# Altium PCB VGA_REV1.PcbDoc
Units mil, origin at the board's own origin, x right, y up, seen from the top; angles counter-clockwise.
Board outline 4435 x 3240 mil, 4 copper layers (Top Layer, MidLayer1, InternalPlane1, Bottom Layer); 47 components, 28 nets, 151 pads, 48 vias.
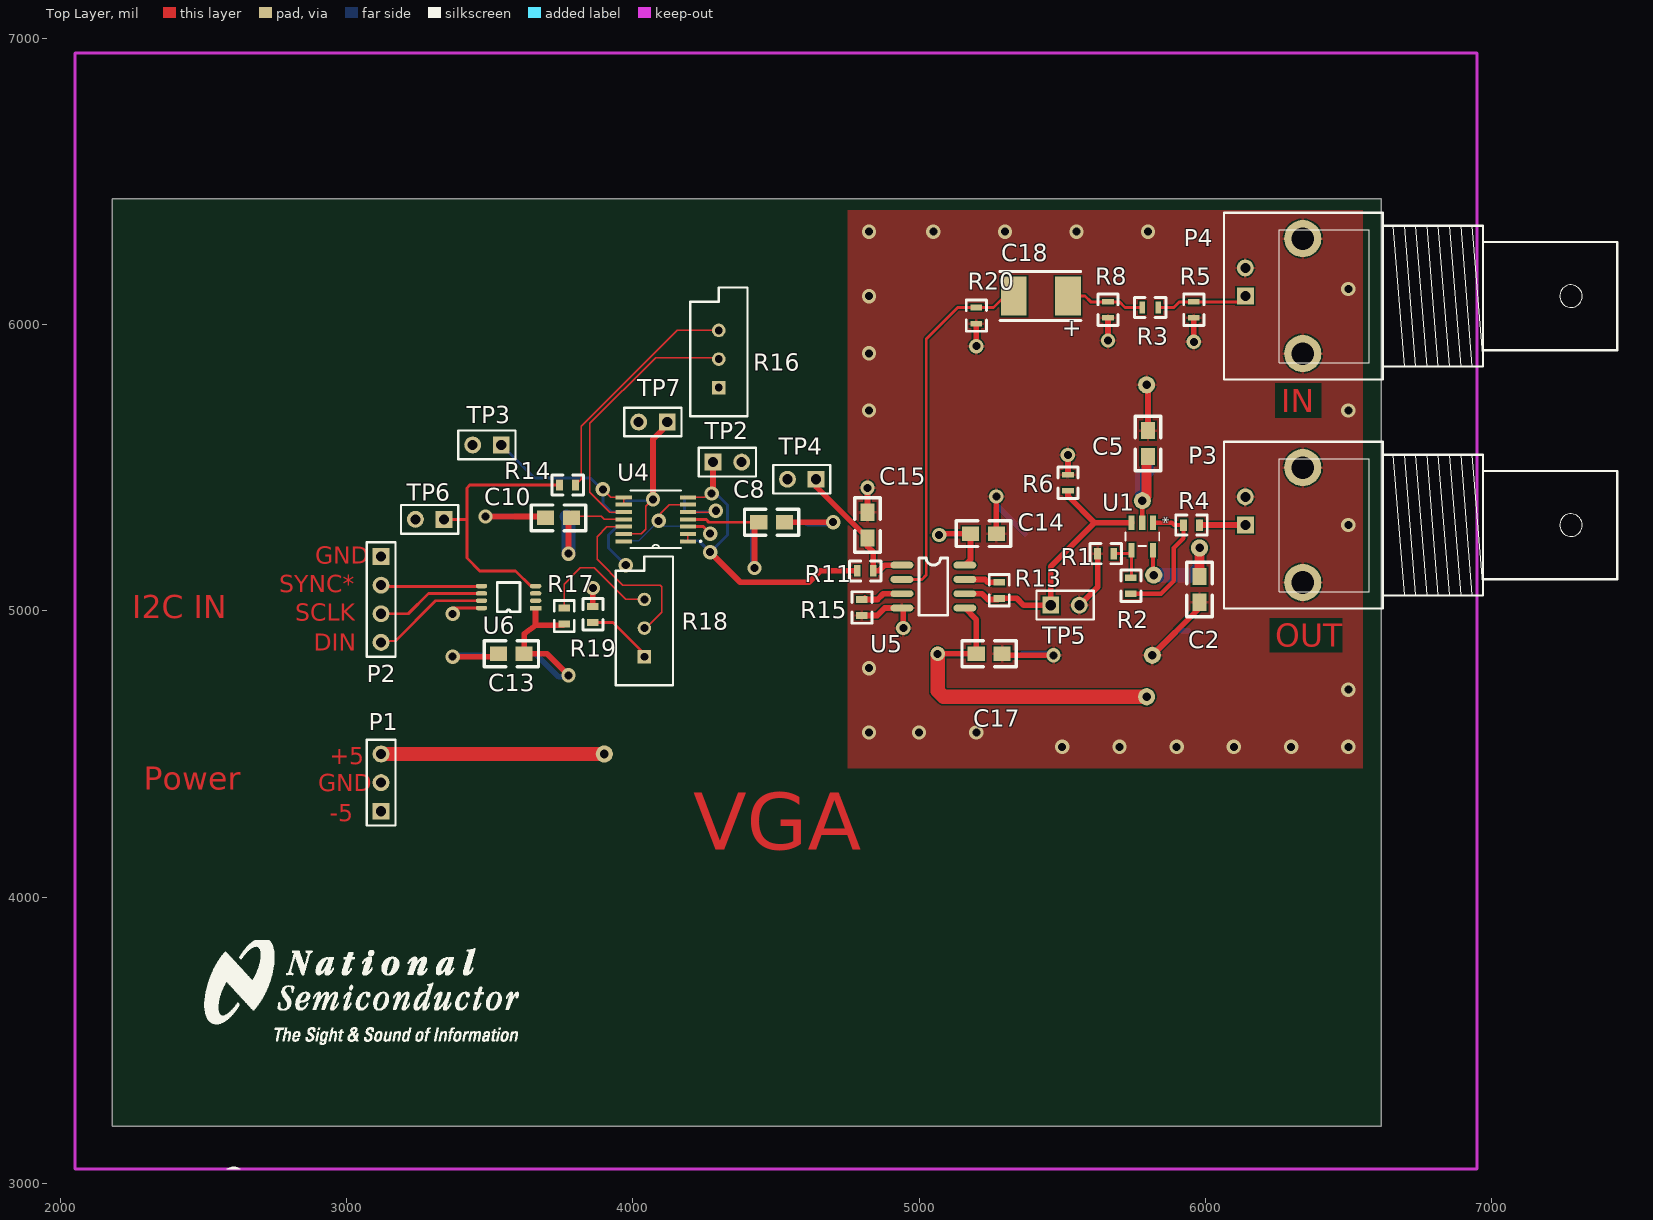
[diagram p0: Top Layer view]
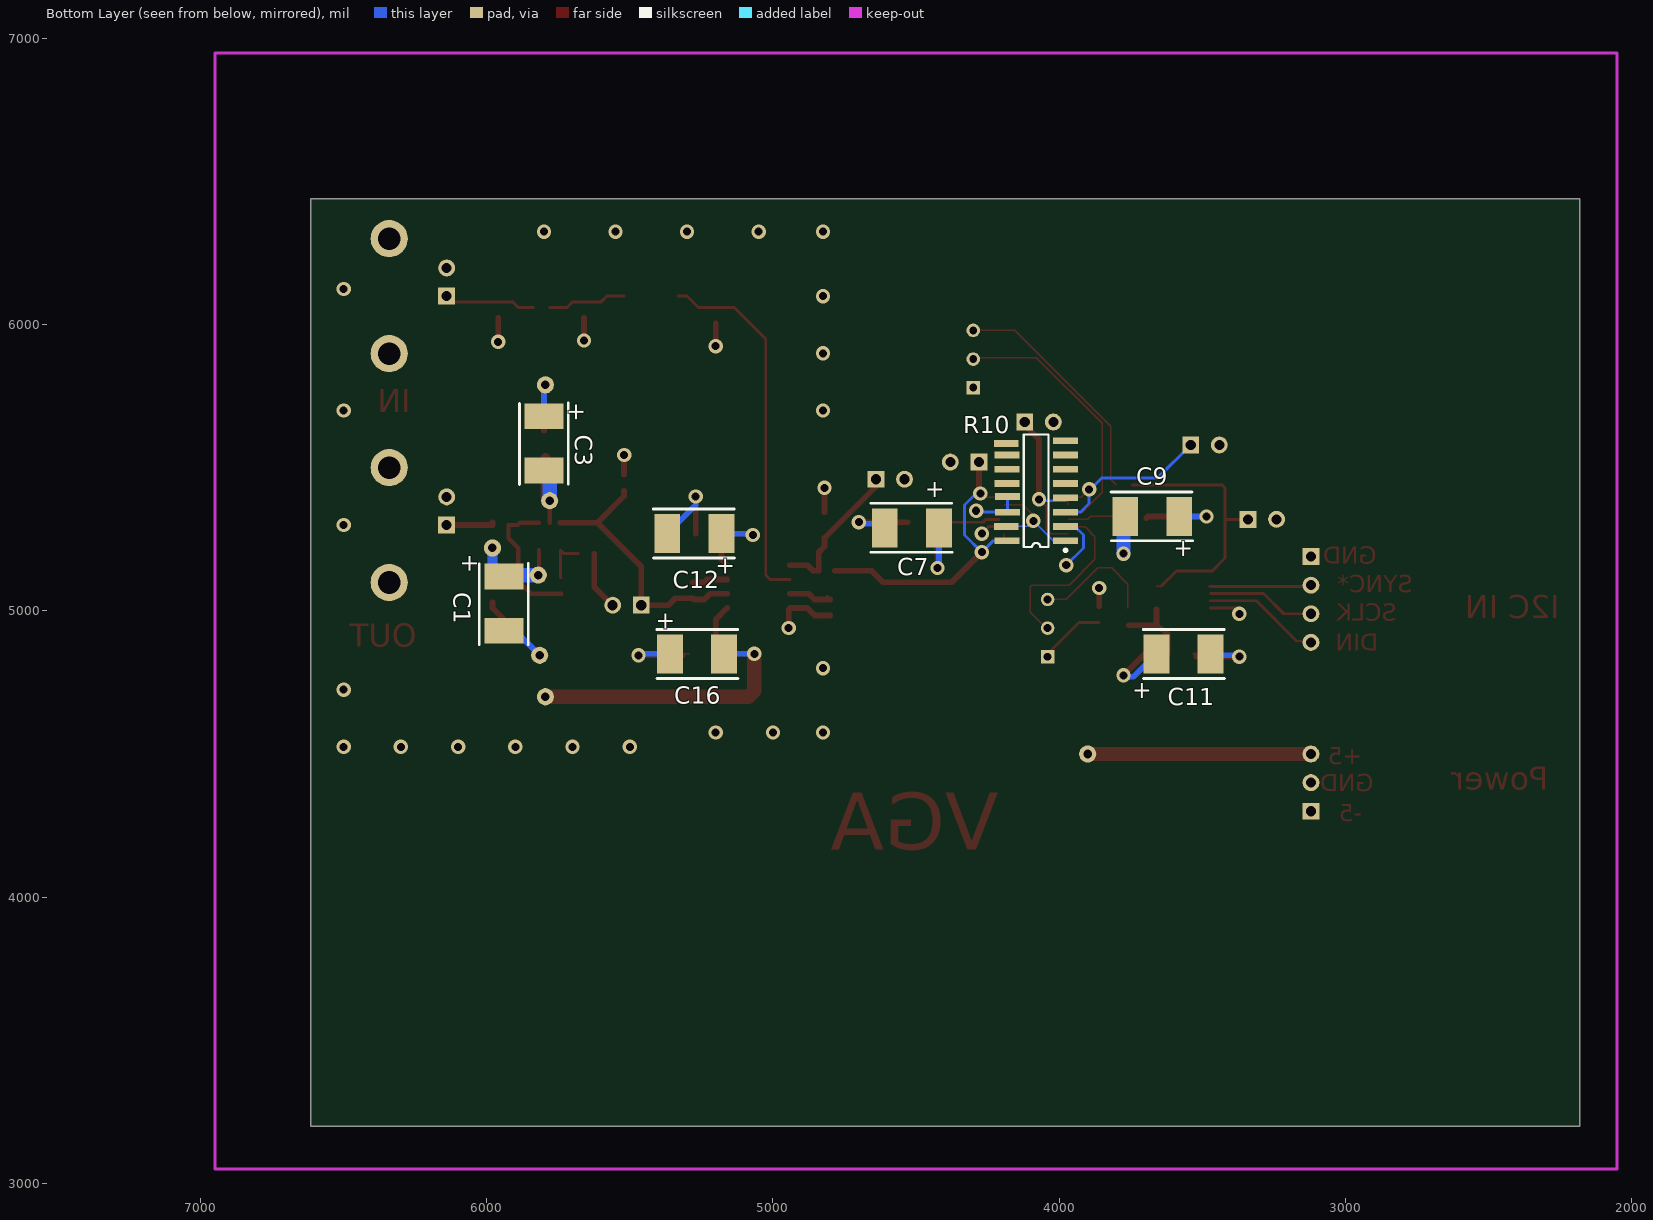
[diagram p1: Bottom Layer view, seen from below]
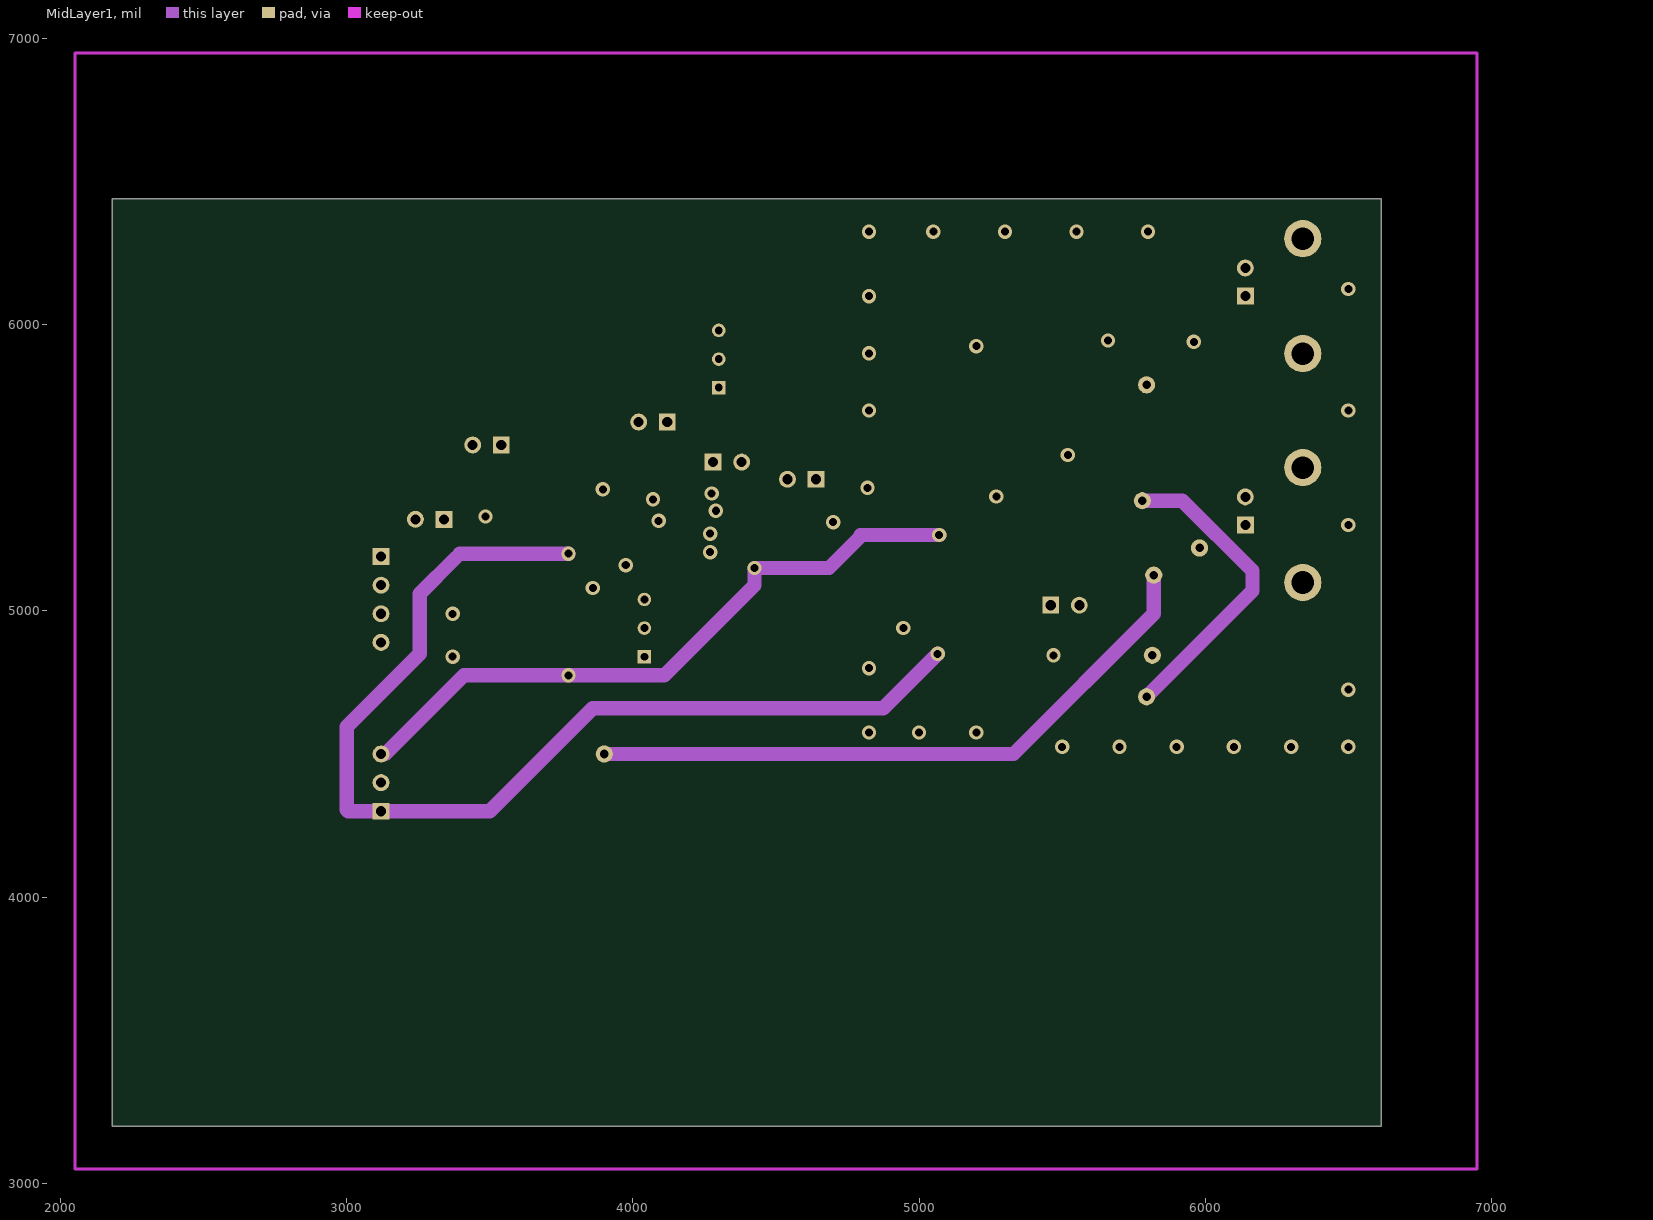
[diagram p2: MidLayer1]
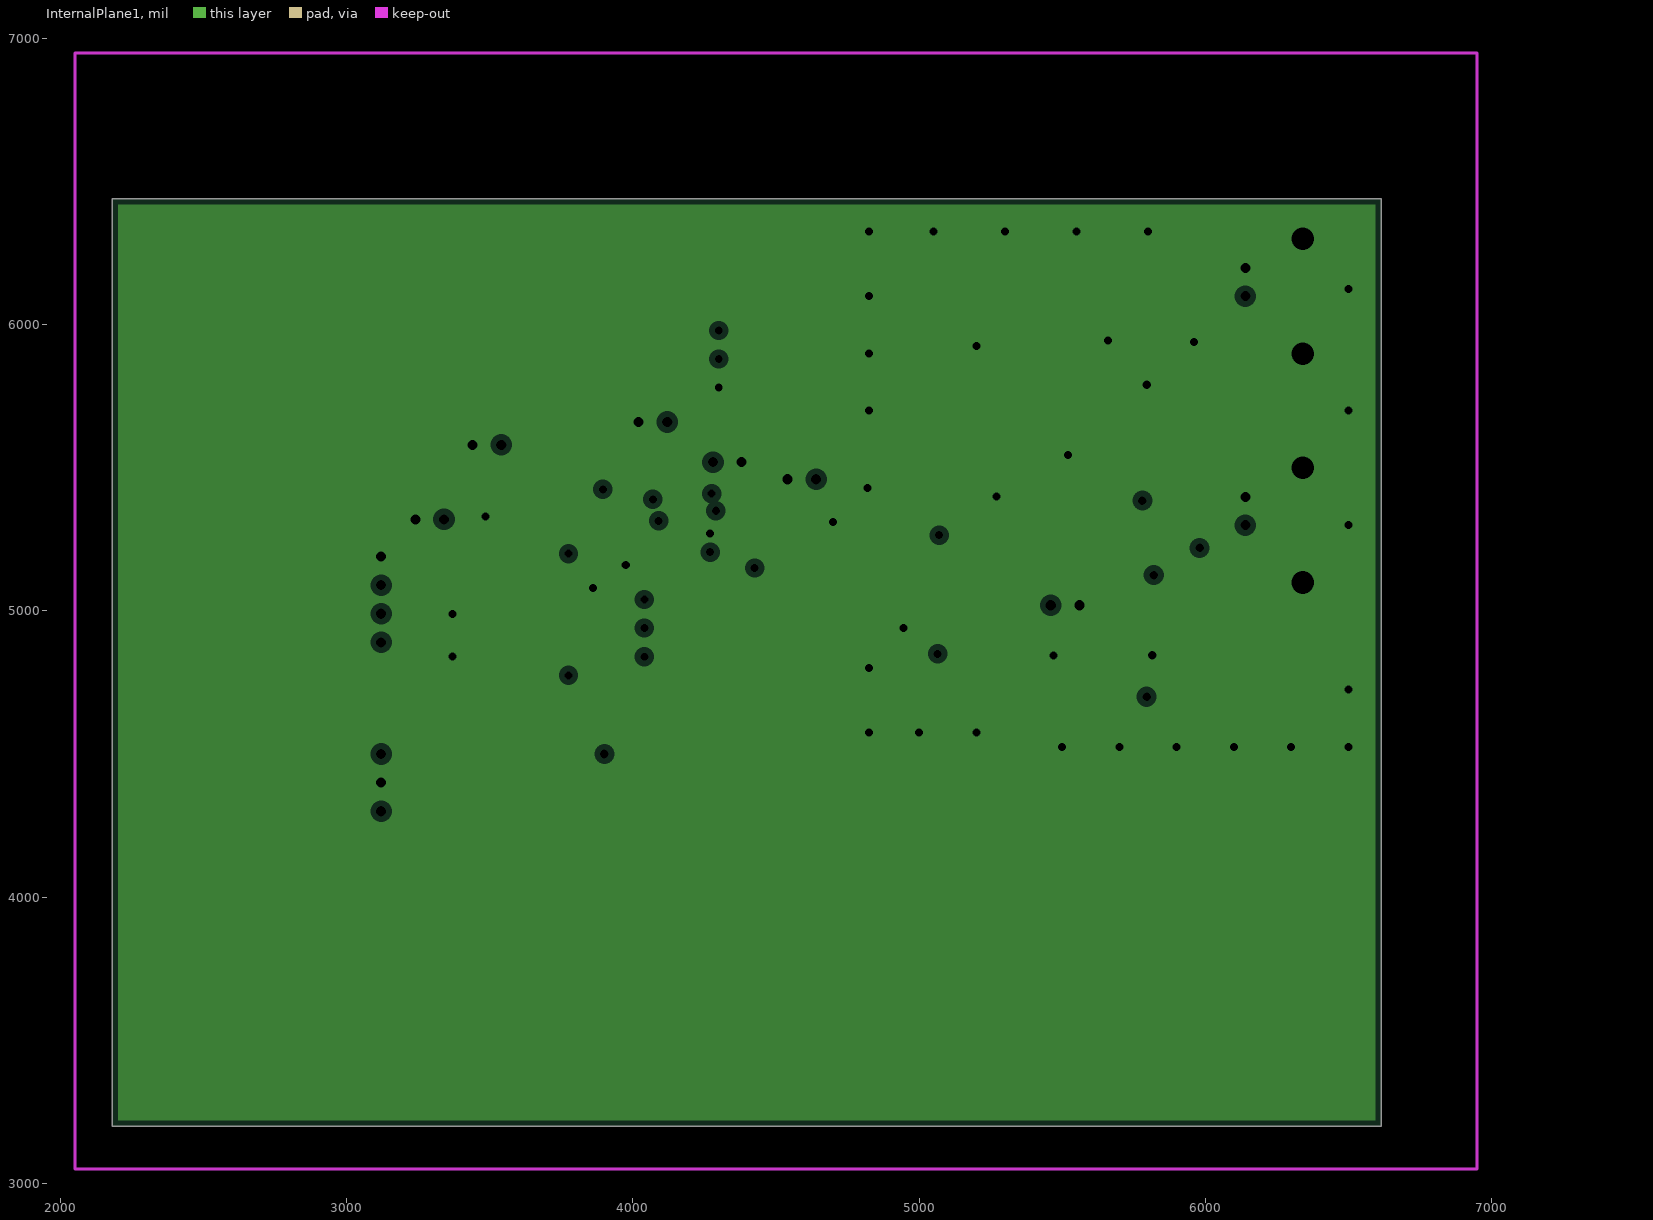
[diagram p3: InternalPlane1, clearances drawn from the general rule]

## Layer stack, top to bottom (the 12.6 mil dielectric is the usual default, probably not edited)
Top Layer: signal copper 1.4
Dielectric: core 12.6, FR-4, Dk 4.8
MidLayer1: signal copper 1.4
Dielectric: prepreg 12.6, FR-4, Dk 4.8
InternalPlane1: plane copper 1.4, net GND
Dielectric: core 12.6, FR-4, Dk 4.8
Bottom Layer: signal copper 1.4

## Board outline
6615,3200 6615,6440 2180,6440 2180,3200

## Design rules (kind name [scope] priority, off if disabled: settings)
Clearance [All] p1: gap=5
ComponentClearance [All] p1: gap=5 collisioncheckmode=3 verticalgap=5
PlaneClearance [All] p1: clearance=20
PlaneConnect [All] p1: planeconnectstyle=Relief reliefexpansion=20 reliefentries=4 reliefconductorwidth=10 reliefairgap=10
PolygonConnect [All] p1: connectstyle=Relief reliefconductorwidth=10 reliefentries=4 polygonreliefangle="90 Angle"
RoutingVias [All] p1: holewidth=25 width=40 viastyle="Through Hole" minholewidth=28 minwidth=50 maxholewidth=28 maxwidth=50
SolderMaskExpansion [All] p1: expansion=4
TestPointUsage [All] p1: valid=0 allowmultiple=FALSE
Testpoint [All] p1: side=15 testpointundercomponent=TRUE minsize=40 maxsize=100 preferedsize=60 minholesize=0 maxholesize=40 preferedholesize=32 testpointgrid=1 style=1023 order=0123456789
Width "Width for V+" [(InNet('V+'))] p1: maxlimit=50 minlimit=10 preferedwidth=10 midlayer1_prefwidth=50 minimp=50.000000 maximp=50.000000 favimp=50.000000
Width [All] p2: maxlimit=50 minlimit=5 preferedwidth=5 minimp=50.000000 maximp=50.000000 favimp=50.000000
16 further rules are at their usual default settings.

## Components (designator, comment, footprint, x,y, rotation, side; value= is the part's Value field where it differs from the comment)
C1 "Cap Pol1" TANT-C 5940,5120 r270 bottom
C2 "Cap" 0805 5980,5120 r270 top
C3 "Cap Pol1" TANT-C 5800,5680 r270 bottom
C5 "Cap" 0805 5800,5540 r90 top
C7 "Cap Pol1" TANT-C 4420,5290 r0 bottom
C8 "Cap" 0805 4440,5310 r0 top
C9 "Cap Pol1" TANT-C 3580,5330 r0 bottom
C10 "Cap" 0805 3785,5325 r180 top
C11 "Cap Pol1" TANT-C 3660,4850 r180 bottom
C12 "Cap Pol1" TANT-C 5180,5270 r0 bottom
C13 "Cap" 0805 3620,4850 r180 top
C14 "Cap" 0805 5180,5270 r0 top
C15 "Cap" 0805 4820,5345 r270 top
C16 "Cap Pol1" TANT-C 5360,4850 r180 bottom
C17 "Cap" 0805 5200,4850 r0 top
C18 "100uF" TANT-C 5520,6100 r180 top
P1 "3 Pin" HDR1X3 3120,4300 r90 top
P2 "4 PIN" HDR1X4 3120,5190 r270 top
P3 "75 OHM BNC" "BNC_RA CON" 6140,5300 r180 top
P4 "75 OHM BNC" "BNC_RA CON" 6140,6100 r180 top
R1 "499" 0603#1 5680,5200 r180 top
R2 "499" 0603#1 5740,5060 r90 top
R3 "140" 0603#2 5780,6060 r0 top
R4 "75" 0603#1 5980,5300 r180 top
R5 "124" 0603#2 5960,6080 r270 top
R6 "100" 0603#2 5520,5420 r90 top
R8 "124" 0603#2 5660,6080 r270 top
R10 "1K" SOIC16 4080,5420 r90 bottom
R11 "1K" 0603#1 4840,5140 r180 top
R13 "1K" 0603#1 5280,5100 r270 top
R14 "24.3k" 0603#1 3800,5440 r180 top
R15 "1K" 0603#1 4800,5040 r270 top
R16 "1K" VR5 4300,5880 r90 top
R17 "9.53K" 0603#1 3760,5010 r270 top
R18 "1K" VR5 4040,4940 r90 top
R19 "2K" 0603#1 3860,4960 r90 top
R20 "10k" 0603#2 5200,6060 r270 top
TP2 "2 Pin" HDR1X2 4280,5520 r0 top
TP3 "2 Pin" HDR1X2 3540,5580 r180 top
TP4 "2 Pin" HDR1X2 4640,5460 r180 top
TP5 "2 Pin" HDR1X2 5460,5020 r0 top
TP6 "2 Pin" HDR1X2 3340,5320 r180 top
TP7 "2 Pin" HDR1X2 4120,5660 r180 top
U1 "LMH6714MF" MF05A 5780,5260 r270 top
U4 "LMP7704MT" MTC14 4080,5320 r180 top
U5 "LMH6505MA" SO-8 4940,5160 r0 top
U6 "DAC081S101" MSOP-8 3660,5010 r180 top

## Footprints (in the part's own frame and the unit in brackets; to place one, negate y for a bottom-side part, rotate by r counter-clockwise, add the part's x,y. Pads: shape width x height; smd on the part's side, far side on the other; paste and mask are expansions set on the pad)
0603#1 [mil]
  rect 24x40 smd: 1(0,0) 2(56,0)
  silkscreen extent -27,-35 83,35
0603#2 [mil]
  rect 19.68x41.34 smd: 1(0,0) 2(55.98,0)
  silkscreen extent -27,-35 83,35
0805 [mil]
  rect 60x50 smd: 1(0,0) 2(90,0)
  silkscreen extent -50,-45 140,45
"BNC_RA CON" [mm] "Connector; BNC Elbow"
  rect 1.5x1.5 hole 0.9: 1(0,0)
  round 3.3 hole 2: 2(-5.1,5.1) 2(-5.1,-5.1)
  round 1.5 hole 0.9: 2(0,-2.5)
  silkscreen extent -33,-7.4 1.9,7.4
HDR1X2 [mm] "Connector; Header; 2 Position"
  rect 1.5x1.5 hole 0.9: 1(0,0)
  round 1.5 hole 0.9: 2(2.54,0)
  silkscreen extent -1.27,-1.27 3.81,1.27
HDR1X3 [mm] "Connector; Header; 3 Position"
  rect 1.5x1.5 hole 0.9: 1(0,0)
  round 1.5 hole 0.9: 2(2.54,0) 3(5.08,0)
  silkscreen extent -1.27,-1.27 6.35,1.27
HDR1X4 [mm] "Connector; Header; 4 Position"
  rect 1.5x1.5 hole 0.9: 1(0,0)
  round 1.5 hole 0.9: 2(2.54,0) 3(5.08,0) 4(7.62,0)
  silkscreen extent -1.27,-1.27 8.89,1.27
MF05A [mil]
  rect 50x22 smd: 1(-48,37.5) 2(-48,0) 3(-48,-37.5) 4(48,-37.5) 5(48,37.5)
  silkscreen extent -15,-59 33,59
MSOP-8 [mil]
  rect 40x15.98 smd: 1(0,0)
  oval 40x16 smd: 2(0,-25.6) 3(0,-51.2) 4(0,-76.8) 5(189,-76.8) 6(189,-51.2) 7(189,-25.6) 8(189,0)
  silkscreen extent 55,-90 134,13
MTC14 [mil]
  rect 56x14 smd: 1(-112,76.77) 2(-112,51.18) 3(-112,25.59) 4(-112,0) 5(-112,-25.59) 6(-112,-51.18) 7(-112,-76.77) 8(112,-76.77) 9(112,-51.18) 10(112,-25.59) 11(112,0) 12(112,25.59) 13(112,51.18) 14(112,76.77)
  silkscreen extent -160,-101 89,101
SO-8 [mil]
  oval 80x24 smd: 1(0,0) 2(0,-50) 3(0,-100) 4(0,-150) 5(220,-150) 6(220,-100) 7(220,-50) 8(220,0)
  silkscreen extent 60,-175 160,25
SOIC16 [mm] "Small Outline; 16 Leads; Body Width 3.9 mm; Pitch 1.27 mm"
  rect 0.6x2.2 smd: 1(-4.445,-2.6) 2(-3.175,-2.6) 3(-1.905,-2.6) 4(-0.635,-2.6) 5(0.635,-2.6) 6(1.905,-2.6) 7(3.175,-2.6) 8(4.445,-2.6) 9(4.191,2.667) 10(3.175,2.6) 11(1.905,2.6) 12(0.635,2.6) 13(-0.508,2.54) 14(-1.905,2.54) 15(-3.175,2.667) 16(-4.445,2.6)
  silkscreen extent -5.42,-2.72 5,1.1
TANT-C [mil]
  rect 90x136 smd: 1(0,0) 2(189,0)
  silkscreen extent -46,-86 238,85
VR5 [mm] "Potentiometer; 3 Leads"
  rect 1.2x1.2 hole 0.7: 1(-2.54,0)
  round 1.2 hole 0.7: 2(0,0) 3(2.54,0)
  silkscreen extent -5.08,-2.54 6.35,2.54

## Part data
C1 C3 C7 C9 C11 C12 C16: "Polarized Capacitor (Radial)"
C2 C5 C8 C10 C13 C14 C15 C17: "Capacitor"
C18: library part WB_CAP_POLARIZED, "Tantalum SMT"
P1: library part "Header 3", "Header, 3-Pin"
P2: library part "Header 4", "Header, 4-Pin"
P3 P4: library part BNC, "BNC Elbow Connector"
R1 R2 R3 R4 R5 R6 R8 R11 R13 R14 R15 R17 R19: library part WB_RESISTOR, "Resistor"
R10: library part "Res Pack1", "Isolated Resistor Network - Parts"
R16 R18: library part RPot, "Potentiometer"
R20: library part WB_RESISTOR, "Resistor, SMD, 0603"
TP2 TP3 TP4 TP5 TP6 TP7: library part "Header 2", "Header, 2-Pin"
U1: "Single Wideband Video Op Amp"
U4: "Precision, CMOS Input, RRIO, Wide Supply Range Amplifiers"
U5: "Wideband, Low Power, Linear-in-dB, Variable Gain  Amplifier"
U6: "DAC"

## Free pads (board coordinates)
  round 60 hole 30: 4(5780,5385) 5(5820,5125) 6(3900,4500) 7(5795,4700) 8(5795,5790) 9(5815,4845) 10(5980,5220)

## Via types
v1: diameter 50, hole 28, Top Layer to Bottom Layer, 48 vias

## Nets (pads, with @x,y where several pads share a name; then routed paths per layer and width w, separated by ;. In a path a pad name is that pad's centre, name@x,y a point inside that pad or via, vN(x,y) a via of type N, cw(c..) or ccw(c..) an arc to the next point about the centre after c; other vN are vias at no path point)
GND: C1.2 C2.2 C3.1 C5.2 C7.2 C8.2 C9.1 C10.2 C11.2 C12.2 C13.2 C14.2 C15.1 C16.1 C17.2 P1.2 P2.1 P3.2 P4.2 pad.8 pad.9 R1.2 R5.2 R6.2 R8.2 R10.2 R15.2 R16.1 R19.2 R20.2 TP2.2 TP3.2 TP4.2 TP5.2 TP6.2 TP7.2 U4.3 U5.4 U6.8 | length 3435.1
  Top Layer w5: v1(3485,5330) v1@3490,5325 ; v1(4270,5270) v1@4270,5285 ; v1@4940,4945 v1(4945,4940) ; C17.2 5310,4850 C17.2@5315,4845
  Top Layer w8: C13.2@3520,4840 C13.2 C13.2@3520,4850
  Top Layer w10: v1@3370,5010 U6.8 ; U4.3 4245.59,5294.41 v1(4270,5270)
  Top Layer w20: v1(3370,4840) C13.2@3520,4840 ; v1(3485,5330) 3690,5330 C10.2 ; R19.2 v1(3860,5080) ; C8.2 v1(4700,5310) ; R15.2 4854,4984 4880,5010 U5.4 4945,5005 v1(4945,4940) ; C15.1 v1(4820,5430) ; v1(5200,5925) R20.2 ; C14.2 v1(5270,5400) ; C17.2@5315,4845 v1(5470,4845) ; R6.2 v1(5520,5545) ; TP5.2 5624,5084 R1.2 ; v1(5660,5945) R8.2 ; pad.8 5800,5785 C5.2 ; pad.9 5980,5010 C2.2 ; v1(5960,5940) R5.2
  Bottom Layer w5: R10.2@3945,5295 R10.2 ; v1@5465,4850 v1(5470,4845)
  Bottom Layer w8: v1(3370,4840) v1@3375,4845
  Bottom Layer w10: R10.2@3945,5295 3915,5265 3915,5220 v1(3975,5160)
  Bottom Layer w20: v1@3375,4845 C11.2@3471,4845 ; v1(3485,5330) C9.1 ; C7.2@4610,5305 v1@4695,5305 ; v1(5270,5400) 5270,5369 C12.2 ; C16.1 v1@5465,4850 ; pad.8 5800,5785 C3.1 ; pad.9 5901,4931 C1.2
  other v1: 5500,4525 5700,4525 5900,4525 6100,4525 6300,4525 6500,4525 4825,4575 5000,4575 5200,4575 6500,4725 4825,4800 3370,4990 6500,5300 4825,5700 6500,5700 4825,5900 4825,6100 6500,6125 4825,6325 5050,6325 5300,6325 5550,6325 5800,6325
NetC15_2: C15.2 R11.1 TP4.1 U5.1 | length 511.1
  Top Layer w5: TP4.1@4640,5435 TP4.1
  Top Layer w20: TP4.1@4640,5435 C15.2 4820,5225 4840,5205 R11.1 4860,5140 4880,5160 U5.1
NetC18_1: C18.1 R3.1 R8.1 | length 276.6
  Top Layer w10: C18.1 5580,6100 5600,6080 5700,6080 5720,6060 R3.1
NetC18_2: C18.2 R20.1 U5.2 | length 1284.3
  Top Layer w10: U5.2 5010,5110 5025,5125 5025,5950 5135,6060 5260,6060 5300,6100 C18.2
NetP2_2: P2.2 U6.5 | length 350
  Top Layer w8: U6.5@3471,5085 U6.5@3475,5085
  Top Layer w10: P2.2@3125,5085 U6.5@3471,5085
NetP2_3: P2.3 U6.6 | length 380.5
  Top Layer w10: P2.3 3215,4990 3286.2,5061.2 U6.6
NetP2_4: P2.4 U6.7 | length 394.2
  Top Layer w8: P2.4@3135,4895 3170,4895
  Top Layer w10: 3170,4895 3310.6,5035.6 U6.7
Netp3_1: P3.1 R4.1 | length 170
  Top Layer w20: R4.1@5980,5310 R4.1 P3.1
NetP4_1: P4.1 R3.2 R5.1 | length 292.3
  Top Layer w10: R3.2 5890,6060 5910,6080 P4.1@6120,6080
NetR1_1: R1.1 R2.2 U1.4 | length 164.5
  Top Layer w10: R1.1 5730.5,5200 U1.4 5742.5,5118.5 R2.2
NetR2_1: R2.1 R4.2 U1.1 | length 487.5
  Top Layer w15: R2.1 5845,5060 5890,5105 5890,5220 5924,5254 R4.2 5891,5300 5883,5308 U1.1
NetR6_1: R6.1 R13.2 TP5.1 U1.3 U5.6 | length 951.3
  Top Layer w20: U5.6 5220,5060 5240,5040 5276,5040 R13.2 5341,5044 5365,5020 TP5.1 5460,5155 5613,5308 ; R6.1 5520,5401 5613,5308 ; U1.3 5613,5308
NetR10_1: R10.1 R10.15 U4.6 | length 381.8
  Top Layer w5: v1(4090,5315) 4090,5335 4126.18,5371.18 U4.6
  Bottom Layer w5: R10.1 4020.71,5245 v1@4090,5314.29 ; v1(4090,5315) v1@4090,5314.29 ; R10.15 4110,5295 4090.71,5314.29 v1@4090,5314.29
NetR10_3: R10.3 TP3.1 U4.8 U4.9 | length 674.6
  Top Layer w5: v1(3895,5425) 3923.23,5396.77 U4.8 U4.9
  Bottom Layer w5: v1@3890,5425 v1(3895,5425)
  Bottom Layer w10: TP3.1 3655,5465 3850,5465 v1@3890,5425 ; v1(3895,5425) 3895,5375 3925,5345 R10.3
NetR10_4: R10.4 TP7.1 U4.13 | length 584.2
  Top Layer w5: U4.13 4028.82,5268.82 4045,5285 4045,5365 v1(4070,5390) ; TP7.1@4120,5650 TP7.1
  Top Layer w20: v1(4070,5390) 4070,5600 TP7.1@4120,5650
  Bottom Layer w5: v1@4065,5385 v1(4070,5390)
  Bottom Layer w10: R10.4@3977.64,5385 v1@4065,5385
NetR10_13: R10.13 R10.14 U4.5 | length 269
  Top Layer w5: U4.5 4285.59,5345.59 v1(4290,5350)
  Bottom Layer w5: v1@4285,5345 v1(4290,5350)
  Bottom Layer w10: R10.14 R10.14@4180,5350 ; R10.13 R10.14@4180,5350 ; v1@4285,5345 4185,5345 4182.5,5347.5 R10.14@4180,5350
NetR10_16: R10.16 R11.2 TP2.1 U4.7 | length 1154.4
  Top Layer w5: U4.7 4251.77,5396.77 4265,5410 v1(4275,5410) ; v1@4265,5400 v1(4275,5410) ; v1@4280,5415 v1(4275,5410)
  Top Layer w20: v1(4270,5205) 4375,5100 4615,5100 4655,5140 R11.2 ; v1@4280,5415 TP2.1
  Bottom Layer w5: v1(4275,5410) v1@4290,5410
  Bottom Layer w10: R10.16 4230,5245 v1(4270,5205) 4330,5265 4330,5370 v1@4290,5410
NetR13_1: R13.1 U5.7 | length 124.1
  Top Layer w20: U5.7 5230,5110 5240,5100 R13.1
NetR14_1: R14.1 R16.3 | length 832
  Top Layer w5: R14.1 3820,5460 3820,5645 4155,5980 R16.3
NetR14_2: R14.2 TP6.1 U6.4 | length 933.8
  Top Layer w5: U6.4@3643.2,5086.8 U6.4
  Top Layer w10: TP6.1 3420,5320 ; U6.4@3643.2,5086.8 3590,5140 3465,5140 3420,5185 3420,5320 ; R14.2 3430,5440 3420,5430 3420,5320
NetR15_1: R15.1 U5.3 | length 162.4
  Top Layer w10: R15.1 R15.1@4810,5050
  Top Layer w20: R15.1 4855,5040 4875,5060 U5.3
NetR16_3: R16.2 U4.10 | length 922
  Top Layer w5: U4.10 3919.41,5345.59 3850,5415 3850,5655 4080,5885 R16.2@4290,5885
NetR17_1: R17.1 R18.3 | length 432.8
  Top Layer w5: R17.1 3760,5094 3816,5150 3865,5150 3975,5040 R18.3
NetR18_1: R18.1 R19.1 | length 235.6
  Top Layer w5: R18.1 R18.1@4040,4850
  Top Layer w10: R19.1 3930,4960 R18.1@4040,4850
NetR18_3: R18.2 U4.12 | length 624.4
  Top Layer w5: U4.12 3909.41,5294.41 3875,5260 3875,5180 3965,5090 4095,5090 4100,5085 4100,4995 4045,4940 R18.2
NetU4_1: U4.1 U4.2 | length 25.6
  Top Layer w5: U4.1 U4.2
V+: C1.1 C2.1 C7.1 C8.1 C11.1 C12.1 C13.1 C14.1 P1.3 pad.5 pad.6 pad.10 R17.2 U1.5 U4.4 U5.8 U6.1 | length 7188.7
  Top Layer w10: U4.4@4210,5320 4255,5320 4265,5310 C8.1@4435,5310
  Top Layer w15: pad.5@5817.5,5127.5 U1.5
  Top Layer w20: U6.1@3660,5005 3660,4950 ; R17.2@3756,4950 3660,4950 ; v1(3775,4775) 3700,4850 C13.1 3620,4920 3660,4950 ; v1(4425,5150) C8.1@4425,5300 ; v1@5075,5270 C14.1 5180,5180 U5.8
  Top Layer w35: C2.1 pad.10
  Top Layer w50: P1.3@3140,4500 pad.6
  MidLayer1 w50: P1.3 3135,4500 3410,4775 v1(3775,4775) 4110,4775 4425,5090 v1(4425,5150) 4685,5150 4795,5260 ; pad.6 5330,4500 5820,4990 pad.5 ; 4795,5265 v1(5070,5265)
  Bottom Layer w20: C11.1 3740,4770 v1@3775,4770 ; v1@4420,5155 C7.1 ; v1@5075,5270 C12.1
  Bottom Layer w35: C1.1 5980,5160 pad.10
  Bottom Layer w50: pad.5 5935,5125 C1.1
V-: C3.2 C5.1 C9.2 C10.1 C16.2 C17.1 P1.1 pad.4 pad.7 U1.2 U4.11 U5.5 | length 6865.9
  Top Layer w5: C10.1@3780,5330 3785,5330 3890,5330 3900,5320 U4.11
  Top Layer w15: U1.2 pad.4
  Top Layer w20: v1(3775,5200) 3775,5315 C10.1@3780,5320 ; v1(5065,4850) C17.1 5200,4970 U5.5
  Top Layer w35: pad.4@5795,5400 C5.1@5795,5535
  Top Layer w50: v1(5065,4850) 5065,4720 5085,4700 pad.7
  MidLayer1 w5: 3000,4295 3005,4300 ; 3405,5185 3405,5200
  MidLayer1 w50: 3000,4305 3000,4595 3255,4850 3255,5060 3380,5185 ; 3005,4300 P1.1 3500,4300 3860,4660 4875,4660 v1(5065,4850) ; 3395,5200 3405,5200 v1(3775,5200) ; pad.4 5920,5385 6165,5140 6165,5070 pad.7
  Bottom Layer w20: v1(5065,4850) C16.2
  Bottom Layer w50: C9.2 3775,5324 v1(3775,5200) ; pad.4 5780,5471 C3.2
pads on no net: R10.5 R10.6 R10.7 R10.8 R10.9 R10.10 R10.11 R10.12 U4.14 U6.2 U6.3

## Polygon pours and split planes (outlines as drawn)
GND on Top Layer (solid): 4750,6400 4750,4450 6550,4450 6550,6400
GND on InternalPlane1 (split plane): 6594.61,3220.39 2200.39,3220.39 2200.39,6419.61 6594.61,6419.61

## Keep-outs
Keep-Out Layer:
  lines w10: 2050,3050 2050,6950 6950,6950 6950,3050 2050,3050

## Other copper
Top Layer:
  text "IN" at 6265,5695 h80
  text "GND" at 2890,5165 h60
  text "SYNC*" at 2765,5065 h60
  text "I2C IN" at 2250,4975 h80
  text "SCLK" at 2820,4965 h60
  text "OUT" at 6245,4875 h80
  text "DIN" at 2885,4860 h60
  text "+5" at 2940,4465 h60
  text "Power" at 2290,4375 h80
  text "GND" at 2900,4370 h60
  text "-5" at 2940,4265 h60
  text "VGA" at 4210,4165 h200

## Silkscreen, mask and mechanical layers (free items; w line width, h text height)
Top Overlay:
  drawing of 5119 lines, arcs and shapes, not listed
